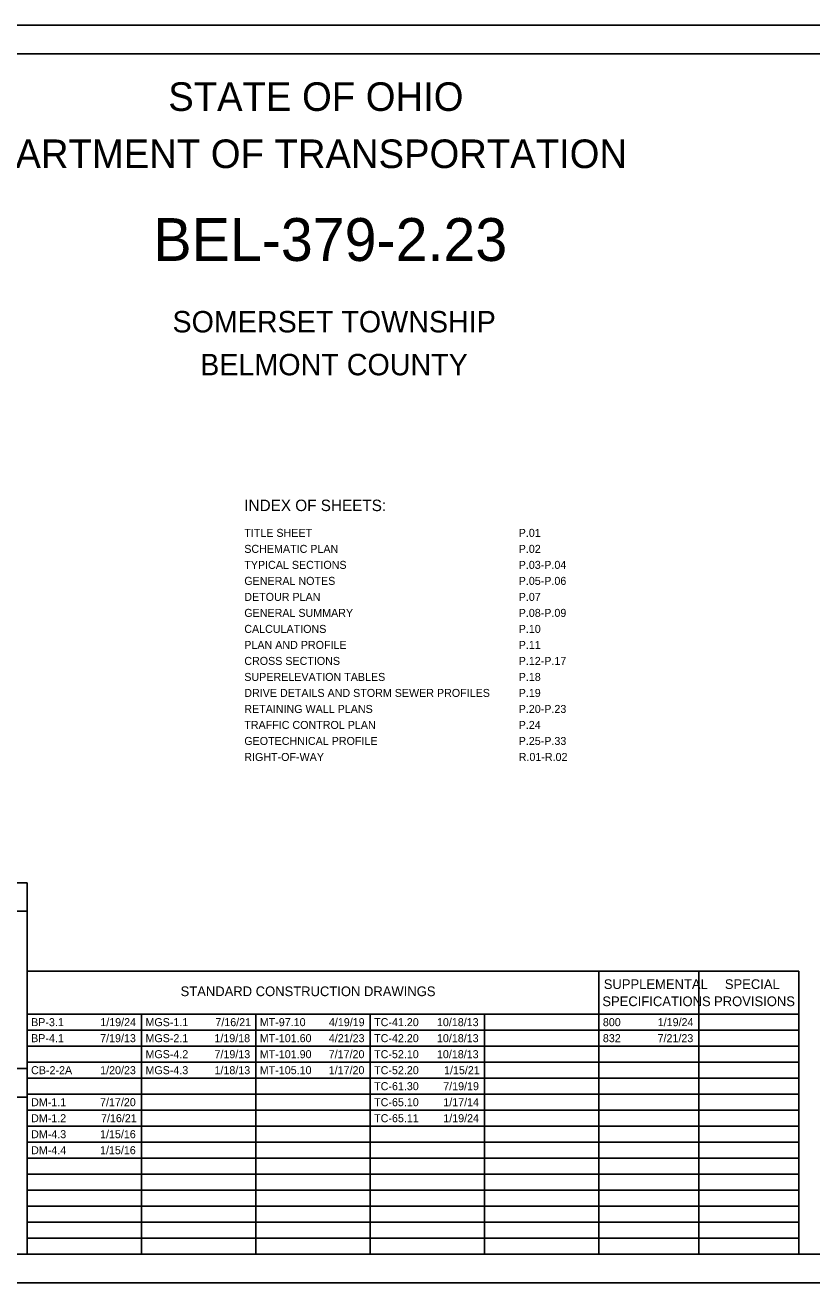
# Model space of a CAD drawing. Extents: x 0 to 2329303, y 0 to 694397.
# Drawn here: x 11.46 to 25.23, y 0 to 22 of the extents above; entities that cross this region are included whole.
import ezdxf

# ---------------------------------------------------------------- set-up
doc = ezdxf.new("R2010")
doc.units = 0
for name, color, linetype in [('SH_Border', 7, 'Continuous'), ('SH_Cut_Line', 7, 'Continuous'), ('SH_Data', 7, 'Continuous')]:
    doc.layers.add(name, color=color, linetype=linetype)

msp = doc.modelspace()

# ---------------------------------------------------------------- linework, layer by layer
at = {"layer": 'SH_Border'}
msp.add_lwpolyline([(1.5, 21.5), (33.5, 21.5), (33.5, 0.5), (1.5, 0.5)], close=True, dxfattribs=at)
at = {"layer": 'SH_Cut_Line'}
msp.add_lwpolyline([(0, 0), (34, 0), (34, 22), (0, 22)], close=True, dxfattribs=at)
at = {"layer": 'SH_Data'}
for p, q in [((8.7, 7), (11.5, 7)), ((11.5, 0.5), (11.5, 7)), ((8.7, 6.5), (11.5, 6.5)), ((11.5, 5.45), (25, 5.45)), ((21.5, 0.5), (21.5, 5.45)), ((23.25, 0.5), (23.25, 5.45)), ((25, 0.5), (25, 5.45)), ((11.5, 4.7), (25, 4.7)), ((13.5, 0.5), (13.5, 4.7)), ((15.5, 0.5), (15.5, 4.7)), ((17.5, 0.5), (17.5, 4.7)), ((19.5, 0.5), (19.5, 4.7)), ((11.5, 4.42), (23.25, 4.42)), ((23.25, 4.42), (25, 4.42)), ((11.5, 4.14), (25, 4.14)), ((21.5, 4.14), (25, 4.14)), ((8.7, 3.75), (11.5, 3.75)), ((11.5, 3.86), (25, 3.86)), ((11.5, 3.58), (25, 3.58)), ((11.5, 3.3), (25, 3.3)), ((8.7, 3.25), (11.5, 3.25)), ((11.5, 3.02), (25, 3.02)), ((11.5, 2.74), (25, 2.74)), ((11.5, 2.46), (25, 2.46)), ((11.5, 2.18), (25, 2.18)), ((11.5, 1.9), (25, 1.9)), ((11.5, 1.62), (25, 1.62)), ((11.5, 1.34), (25, 1.34)), ((11.5, 1.06), (25, 1.06)), ((11.5, 0.78), (25, 0.78))]:
    msp.add_line(p, q, dxfattribs=at)

# ---------------------------------------------------------------- texts
for s, height, p in [('STATE OF OHIO', 0.5, (13.968, 20.5)), ('DEPARTMENT OF TRANSPORTATION', 0.5, (9.92, 19.5)), ('BEL-379-2.23', 0.75, (13.708, 17.875)), ('SOMERSET TOWNSHIP', 0.375, (14.042, 16.625)), ('BELMONT COUNTY', 0.375, (14.527, 15.875)), ('INDEX OF SHEETS:', 0.2, (15.298, 13.5)), ('TITLE SHEET', 0.14, (15.298, 13.049)), ('P.01', 0.14, (20.098, 13.049)), ('SCHEMATIC PLAN', 0.14, (15.298, 12.769)), ('P.02', 0.14, (20.098, 12.769)), ('TYPICAL SECTIONS', 0.14, (15.298, 12.489)), ('P.03-P.04', 0.14, (20.098, 12.489)), ('GENERAL NOTES', 0.14, (15.298, 12.209)), ('P.05-P.06', 0.14, (20.098, 12.209)), ('DETOUR PLAN', 0.14, (15.298, 11.929)), ('P.07', 0.14, (20.098, 11.929)), ('GENERAL SUMMARY', 0.14, (15.298, 11.649)), ('P.08-P.09', 0.14, (20.098, 11.649)), ('CALCULATIONS', 0.14, (15.298, 11.369)), ('P.10', 0.14, (20.098, 11.369)), ('PLAN AND PROFILE', 0.14, (15.298, 11.089)), ('P.11', 0.14, (20.098, 11.089)), ('CROSS SECTIONS', 0.14, (15.298, 10.809)), ('P.12-P.17', 0.14, (20.098, 10.809)), ('SUPERELEVATION TABLES', 0.14, (15.298, 10.529)), ('P.18', 0.14, (20.098, 10.529)), ('DRIVE DETAILS AND STORM SEWER PROFILES', 0.14, (15.298, 10.249)), ('P.19', 0.14, (20.098, 10.249)), ('RETAINING WALL PLANS', 0.14, (15.298, 9.969)), ('P.20-P.23', 0.14, (20.098, 9.969)), ('TRAFFIC CONTROL PLAN', 0.14, (15.298, 9.689)), ('P.24', 0.14, (20.098, 9.689)), ('GEOTECHNICAL PROFILE', 0.14, (15.298, 9.409)), ('P.25-P.33', 0.14, (20.098, 9.409)), ('RIGHT-OF-WAY', 0.14, (15.298, 9.129)), ('R.01-R.02', 0.14, (20.098, 9.129)), ('SUPPLEMENTAL', 0.17, (21.586, 5.14)), ('SPECIAL', 0.17, (23.704, 5.14)), ('STANDARD CONSTRUCTION DRAWINGS', 0.17, (14.184, 5.015)), ('SPECIFICATIONS', 0.17, (21.561, 4.84)), ('PROVISIONS', 0.17, (23.515, 4.84)), ('BP-3.1', 0.14, (11.569, 4.49)), ('1/19/24', 0.14, (12.779, 4.49)), ('MGS-1.1', 0.14, (13.569, 4.49)), ('7/16/21', 0.14, (14.792, 4.49)), ('MT-97.10', 0.14, (15.569, 4.49)), ('4/19/19', 0.14, (16.778, 4.49)), ('TC-41.20', 0.14, (17.569, 4.49)), ('10/18/13', 0.14, (18.668, 4.49)), ('800', 0.14, (21.57, 4.49)), ('1/19/24', 0.14, (22.53, 4.49)), ('BP-4.1', 0.14, (11.569, 4.21)), ('7/19/13', 0.14, (12.777, 4.21)), ('MGS-2.1', 0.14, (13.569, 4.21)), ('1/19/18', 0.14, (14.775, 4.21)), ('MT-101.60', 0.14, (15.569, 4.21)), ('4/21/23', 0.14, (16.777, 4.21)), ('TC-42.20', 0.14, (17.569, 4.21)), ('10/18/13', 0.14, (18.668, 4.21)), ('832', 0.14, (21.57, 4.21)), ('7/21/23', 0.14, (22.527, 4.21)), ('MGS-4.2', 0.14, (13.569, 3.93)), ('7/19/13', 0.14, (14.777, 3.93)), ('MT-101.90', 0.14, (15.569, 3.93)), ('7/17/20', 0.14, (16.775, 3.93)), ('TC-52.10', 0.14, (17.569, 3.93)), ('10/18/13', 0.14, (18.668, 3.93)), ('CB-2-2A', 0.14, (11.569, 3.65)), ('1/20/23', 0.14, (12.777, 3.65)), ('MGS-4.3', 0.14, (13.569, 3.65)), ('1/18/13', 0.14, (14.777, 3.65)), ('MT-105.10', 0.14, (15.569, 3.65)), ('1/17/20', 0.14, (16.775, 3.65)), ('TC-52.20', 0.14, (17.569, 3.65)), ('1/15/21', 0.14, (18.792, 3.65)), ('TC-61.30', 0.14, (17.569, 3.37)), ('7/19/19', 0.14, (18.778, 3.37)), ('DM-1.1', 0.14, (11.569, 3.09)), ('7/17/20', 0.14, (12.775, 3.09)), ('TC-65.10', 0.14, (17.569, 3.09)), ('1/17/14', 0.14, (18.779, 3.09)), ('DM-1.2', 0.14, (11.569, 2.81)), ('7/16/21', 0.14, (12.792, 2.81)), ('TC-65.11', 0.14, (17.569, 2.81)), ('1/19/24', 0.14, (18.779, 2.81)), ('DM-4.3', 0.14, (11.569, 2.53)), ('1/15/16', 0.14, (12.775, 2.53)), ('DM-4.4', 0.14, (11.569, 2.25)), ('1/15/16', 0.14, (12.775, 2.25))]:
    msp.add_text(s, height=height, dxfattribs=at).set_placement(p)

doc.saveas('drawing.dxf')
